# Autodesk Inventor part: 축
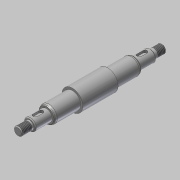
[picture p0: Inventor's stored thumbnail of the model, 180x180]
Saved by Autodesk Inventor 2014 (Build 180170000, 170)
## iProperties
Created: 2020-05
Part Number: 축
Material: 강철, 연강
Document SubType Name: Modeling
Designer: mduedu
Density: 1 g/cm^3
Appearance: 강철
Author: mduedu
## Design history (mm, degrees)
sketch "스케치1"
  geometry: L1 (0, 0)-(21, 0); L2 (21, 0)-(21, 12.5); L3 (21, 12.5)-(0, 12.5); L4 (0, 12.5)-(0, 0); L5 (21, 0)-(52, 0); L6 (52, 0)-(52, 10); L7 (52, 10)-(21, 10); L8 (21, 10)-(21, 0); L9 (52, 0)-(72, 0); L10 (72, 0)-(72, 7); L11 (72, 7)-(52, 7); L12 (52, 7)-(52, 0); L13 (72, 0)-(86, 0); L14 (86, 0)-(86, 5); L15 (86, 5)-(72, 5); L16 (72, 5)-(72, 0); L17 (0, 0)-(-21, 0); L18 (-21, 0)-(-21, 12.5); L19 (-21, 12.5)-(0, 12.5); L20 (-21, 0)-(-52, 0); L21 (-52, 0)-(-52, 10); L22 (-52, 10)-(-21, 10); L23 (-21, 10)-(-21, 0); L24 (-52, 0)-(-72, 0); L25 (-72, 0)-(-72, 7); L26 (-72, 7)-(-52, 7); L27 (-52, 7)-(-52, 0); L28 (-72, 0)-(-86, 0); L29 (-86, 0)-(-86, 5); L30 (-86, 5)-(-72, 5); L31 (-72, 5)-(-72, 0)
  constraints: 62 end point, 11 symmetric about line, 8 parallel, 4 horizontal, 4 perpendicular
  dimensions: "d0" = 172 distance between parallel lines of L14 L29; "d2" = 25 diameter of L3 L1; "d3" = 20 diameter of L7 L5; "d4" = 14 diameter of L11 L9; "d5" = 10 diameter of L15 L13; "d6" = 42 distance of L2.end L18.end; "d7" = 31 distance of L6.end L7.end; "d8" = 20 distance of L10.end L11.end; "d9" = 14 distance of L14.end L15.end (derived)
revolve "회전1" sketch "스케치1" stored, may be unused: angle "d10" = 90 deg
sketch "스케치2"
  geometry: L1 (72, -5)-(72, -7) reference; L2 (72, -7)-(52, -7) reference; L3 (52, -7)-(52, -10) reference; L4 (52, -10)-(21, -10) reference; L5 (21, -10)-(21, -12.5) reference; L6 (21, -12.5)-(-21, -12.5) reference; L7 (-21, -12.5)-(-21, -10) reference; L8 (-21, -10)-(-52, -10) reference; L9 (-52, -10)-(-52, -7) reference; L10 (-52, -7)-(-72, -7) reference; L11 (-72, -7)-(-72, -5) reference; L12 (-72, -5)-(-86, -5) reference; L13 (-86, -5)-(-86, 5) reference; L14 (-86, 5)-(-72, 5) reference; L15 (-72, 5)-(-72, 7) reference; L16 (-72, 7)-(-52, 7) reference; L17 (-52, 7)-(-52, 10) reference; L18 (-52, 10)-(-21, 10) reference; L19 (-21, 10)-(-21, 12.5) reference; L20 (-21, 12.5)-(21, 12.5) reference; L21 (21, 12.5)-(21, 10) reference; L22 (21, 10)-(52, 10) reference; L23 (52, 10)-(52, 7) reference; L24 (52, 7)-(72, 7) reference; L25 (72, 7)-(72, 5) reference; L26 (72, 5)-(86, 5) reference; L27 (86, 5)-(86, -5) reference; L28 (86, -5)-(72, -5) reference; L29 (-86, 0)-(86, 0); L30 (0, -12.5)-(0, 12.5); L31 (-52, 8.85)-(-50.008, 10); L32 (-50.008, 10)-(-52, 10); L33 (-52, 10)-(-52, 8.85); 1 further point
  constraints: 10 end point, 4 midpoint, 2 collinear, 2 point on line
  dimensions: "d11" = 17.7 diameter of L31.start L29; "d12" = 30 deg angle of L31 L32
revolve "회전2" sketch "스케치2" stored, may be unused: angle "d13" = 90 deg
fillet "모깎기1" dims "d14" = 4, "d15" = 0.5
node "작업 평면1"
sketch "스케치3"
  geometry: L1 (-6, 2.5)-(6, 2.5); L2 (6, 2.5)-(6, -2.5); L3 (6, -2.5)-(-6, -2.5); L4 (-6, -2.5)-(-6, 2.5); L5 (-10, 8.561)-(-10, -8.561) reference; 2 further points
  constraints: 8 end point, 2 parallel, 1 horizontal, 1 horizontal alignment, 1 midpoint, 1 perpendicular
  dimensions: "d16" = 5 distance of L1.end L2.end; "d18" = 4 distance between parallel lines of L4 L5; "d19" = 12 distance of L1.start L1.end
extrude "돌출1" cut sketch "스케치3" distance "d20" = 3; taper "d21" = 0 deg
fillet "모깎기2" dims "d22" = 2.5
fillet "모깎기3" dims "d23" = 2.5
feature "스레드1" dims "d24" = 12, "d25" = 0
feature "스레드2" dims "d26" = 10, "d27" = 0
chamfer "모따기1" distance "d28" = 1; stored, may be unused: second distance "d29" = 2, angle "d30" = 45 deg
chamfer "모따기2" distance "d31" = 1; stored, may be unused: second distance "d32" = 2, angle "d33" = 45 deg
node "솔리드1"
mirror "대칭1"
mirror "대칭2"
node "절단 모서리 투영1"
